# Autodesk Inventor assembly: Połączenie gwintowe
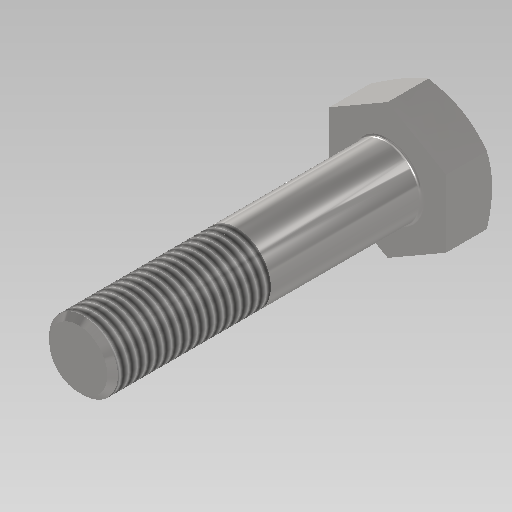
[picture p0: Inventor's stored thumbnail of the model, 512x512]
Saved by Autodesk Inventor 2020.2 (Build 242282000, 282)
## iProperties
Manager: www.cadconsulting.pl
Company: Fabian Stasiak CAD Consulting
ClientObjectVersion: 1
Created: 2019-11
Part Number: Połączenie gwintowe
Document SubType Name: Assembly
Designer: F.Stasiak
Author: F.Stasiak
Subject: Zbiór ćwiczeń. Autodesk Inventor 2020. Kurs podstawowy
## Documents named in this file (2)
- C:\2020_Kurs_podstawowy\R6 Zespoły\BOM\123-500-000\Design Accelerator\Połączenie gwintowe1.iam
- C:\2020_Kurs_podstawowy\Zasoby\Content Center Files\pl-PL\ANSI B18.2.3.6M\ANSI B18.2.3.6M - M20 x 2.5 x 90.ipt
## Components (1 placed, 1 different names)
1. Śruba z łbem sześciokątnym wzmocnionym - Metryczny M20 x 2,5 x 90:1
